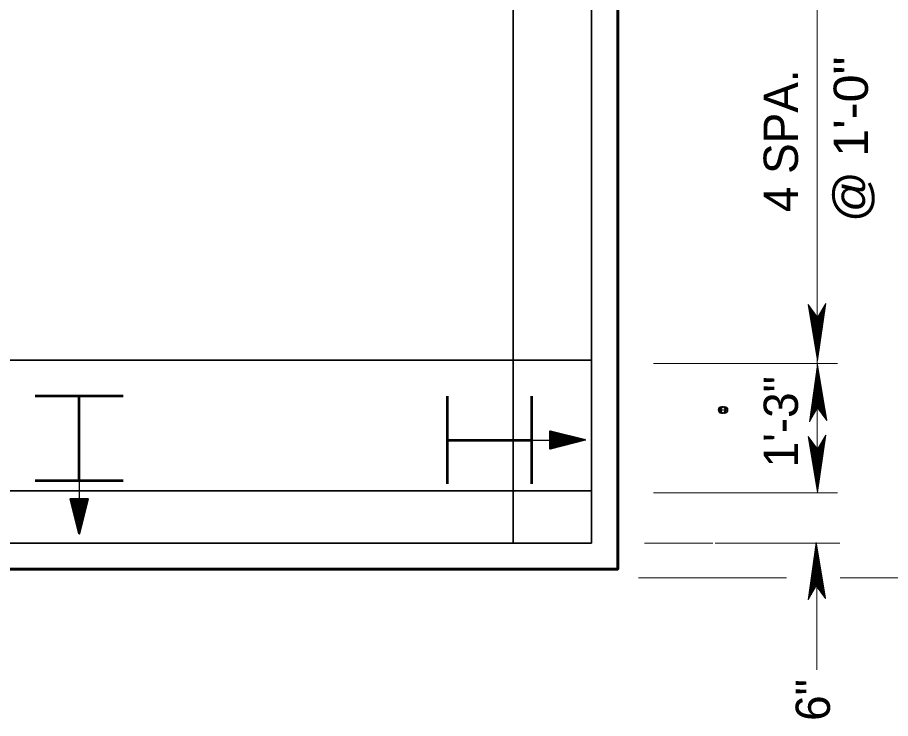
# Model space of a CAD drawing. Extents: x 144 to 252, y 360 to 425.
# Drawn here: x 174.56 to 182.91, y 391.03 to 397.74 of the extents above; entities that cross this region are included whole.
import ezdxf
from ezdxf.enums import TextEntityAlignment as Align

# ---------------------------------------------------------------- set-up
doc = ezdxf.new("R2010")
doc.units = 0
doc.header["$LTSCALE"] = 0.13
doc.header["$PDMODE"] = 32
doc.header["$PDSIZE"] = 0.065
for name, color, linetype, lineweight in [('1', 7, 'Continuous', 40), ('10', 7, 'Continuous', 35), ('16', 7, 'Continuous', 13), ('3', 7, 'Continuous', 13), ('9', 7, 'Continuous', 25)]:
    doc.layers.add(name, color=color, linetype=linetype, lineweight=lineweight)

msp = doc.modelspace()

# ---------------------------------------------------------------- linework, layer by layer
at = {"layer": '1', "lineweight": 35}
for p, q in [((179.2978, 397.8819), (179.2978, 392.7095)), ((179.2978, 395.4595), (179.2978, 395.8819)), ((180.0478, 395.4595), (180.0478, 392.7095)), ((168.4074, 394.4595), (180.0478, 394.4595)), ((168.4074, 393.2095), (180.0478, 393.2095)), ((168.3901, 392.7095), (180.0478, 392.7095))]:
    msp.add_line(p, q, dxfattribs=at)
at = {"layer": '1', "lineweight": 13}
for p, q in [((182.2047, 397.8819), (182.2047, 393.2256)), ((182.2047, 395.4595), (182.2047, 395.8819)), ((182.3986, 394.4261), (180.6381, 394.4261)), ((181.7029, 393.1902), (180.6381, 393.1902)), ((182.3986, 393.1902), (181.4498, 393.1902)), ((181.2062, 392.7091), (180.5544, 392.7091)), ((182.4215, 392.7091), (181.2307, 392.7091)), ((182.2047, 392.6491), (182.2047, 392.3438)), ((182.2006, 392.5937), (182.2006, 391.4952)), ((181.9128, 392.3779), (180.4962, 392.3779)), ((184.4158, 392.3779), (182.4244, 392.3779))]:
    msp.add_line(p, q, dxfattribs=at)
at = {"layer": '1', "lineweight": 60}
for p, q in [((180.2978, 395.8819), (180.2978, 395.4595)), ((180.2978, 392.4595), (180.2978, 395.8819)), ((180.2978, 393.9828), (180.2978, 392.4595)), ((180.2978, 392.4595), (156.2978, 392.4595)), ((156.2978, 392.4595), (180.2978, 392.4595))]:
    msp.add_line(p, q, dxfattribs=at)
at = {"layer": '1', "lineweight": 53}
for p, q in [((174.7277, 394.1175), (175.5673, 394.1175)), ((175.1474, 393.3092), (175.1474, 394.1175)), ((178.6658, 394.1148), (178.6658, 393.2752)), ((179.4742, 394.1148), (179.4742, 393.2752)), ((178.6658, 393.695), (179.4742, 393.695)), ((174.7276, 393.3092), (175.5672, 393.3092))]:
    msp.add_line(p, q, dxfattribs=at)
at = {"layer": '1', "lineweight": 25}
for p, q in [((179.4742, 393.695), (179.9742, 393.695)), ((175.1474, 393.3092), (175.1474, 392.8092))]:
    msp.add_line(p, q, dxfattribs=at)
at = {"layer": '1', "lineweight": 35}
msp.add_lwpolyline([(180.0478, 395.4595), (180.0478, 397.8819), (180.0478, 400.2095)], dxfattribs=at)
at = {"layer": '1', "lineweight": 60}
msp.add_lwpolyline([(156.2978, 392.4595), (180.2978, 392.4595), (180.2978, 397.8819)], dxfattribs=at)
at = {"layer": '10'}
for p, q in [((179.652, 393.7432), (179.8246, 393.7359)), ((179.8359, 393.7103), (179.652, 393.718)), ((179.8358, 393.704), (179.652, 393.7117)), ((179.652, 393.7054), (179.8357, 393.6977)), ((179.8355, 393.6915), (179.652, 393.6992)), ((179.652, 393.6954), (179.9872, 393.6954)), ((175.1439, 392.9478), (175.1516, 393.1313)), ((175.1478, 393.1313), (175.1478, 392.7961)), ((175.1578, 393.1313), (175.1502, 392.9477)), ((175.1564, 392.9475), (175.1642, 393.1313)), ((175.1627, 392.9474), (175.1704, 393.1313)), ((175.1956, 393.1313), (175.1883, 392.9588))]:
    msp.add_line(p, q, dxfattribs=at)
for points in [[(179.652, 393.6119), (179.652, 393.7788), (179.9872, 393.6955)], [(179.652, 393.6119), (179.9872, 393.6955), (179.652, 393.6119)], [(175.0643, 393.1313), (175.2312, 393.1313), (175.1479, 392.7961)], [(175.0643, 393.1313), (175.1479, 392.7961), (175.0643, 393.1313)]]:
    msp.add_lwpolyline(points, dxfattribs=at)
for points in [[(179.9872, 393.6955), (179.652, 393.6119), (179.652, 393.7788), (179.652, 393.6119)], [(175.1479, 392.7961), (175.0643, 393.1313), (175.2312, 393.1313), (175.0643, 393.1313)]]:
    msp.add_lwpolyline(points, close=True, dxfattribs=at)
at = {"layer": '3'}
for p, q in [((182.2086, 394.4528), (182.1193, 394.9905)), ((182.1193, 394.9905), (182.2084, 394.868)), ((182.2079, 394.4672), (182.1217, 394.9872)), ((182.2079, 394.4781), (182.124, 394.984)), ((182.2079, 394.4925), (182.1272, 394.9797)), ((182.2079, 394.5052), (182.1298, 394.976)), ((182.2828, 394.9956), (182.2079, 394.4672)), ((182.2808, 394.9921), (182.2079, 394.4781)), ((182.2782, 394.9875), (182.2079, 394.4925)), ((182.2757, 394.9834), (182.2079, 394.5052)), ((182.2757, 394.9834), (182.2079, 394.5052)), ((182.2736, 394.9797), (182.2079, 394.5166)), ((182.2084, 394.868), (182.2863, 395.0016)), ((182.2863, 395.0016), (182.2086, 394.4528)), ((182.2079, 394.5166), (182.1322, 394.9727)), ((182.2079, 394.531), (182.1354, 394.9684)), ((182.2079, 394.5437), (182.1382, 394.9647)), ((182.2079, 394.5575), (182.1411, 394.9606)), ((182.2079, 394.5713), (182.1441, 394.9565)), ((182.2079, 394.5846), (182.1469, 394.9526)), ((182.2079, 394.5985), (182.1499, 394.9485)), ((182.2079, 394.6111), (182.1526, 394.9447)), ((182.2079, 394.6225), (182.1551, 394.9413)), ((182.2079, 394.6382), (182.1584, 394.9367)), ((182.2079, 394.652), (182.1614, 394.9327)), ((182.2074, 394.67), (182.1645, 394.9284)), ((182.2074, 394.6839), (182.1675, 394.9242)), ((182.2074, 394.6971), (182.1703, 394.9204)), ((182.2079, 394.7062), (182.1731, 394.9167)), ((182.2079, 394.7182), (182.1757, 394.9131)), ((182.2079, 394.732), (182.1787, 394.909)), ((182.2079, 394.7477), (182.1819, 394.9043)), ((182.2079, 394.7602), (182.1847, 394.9007)), ((182.2079, 394.7735), (182.1875, 394.8967)), ((182.2079, 394.7855), (182.1902, 394.8932)), ((182.2441, 394.9292), (182.2074, 394.67)), ((182.2415, 394.9247), (182.2074, 394.6839)), ((182.239, 394.9205), (182.2074, 394.6971)), ((182.2709, 394.9752), (182.2079, 394.531)), ((182.2685, 394.9711), (182.2079, 394.5437)), ((182.266, 394.9667), (182.2079, 394.5575)), ((182.2634, 394.9622), (182.2079, 394.5713)), ((182.2609, 394.958), (182.2079, 394.5846)), ((182.2583, 394.9535), (182.2079, 394.5985)), ((182.256, 394.9495), (182.2079, 394.6111)), ((182.2537, 394.9457), (182.2079, 394.6225)), ((182.2509, 394.9407), (182.2079, 394.6382)), ((182.2482, 394.9363), (182.2079, 394.652)), ((182.2382, 394.919), (182.2079, 394.7062)), ((182.2359, 394.9151), (182.2079, 394.7182)), ((182.2332, 394.9107), (182.2079, 394.732)), ((182.2304, 394.9057), (182.2079, 394.7477)), ((182.228, 394.9016), (182.2079, 394.7602)), ((182.2255, 394.8973), (182.2079, 394.7735)), ((182.2233, 394.8935), (182.2079, 394.7855)), ((182.246, 394.9323), (182.209, 394.6716)), ((182.2079, 394.8), (182.1932, 394.8889)), ((182.2079, 394.8138), (182.1962, 394.8847)), ((182.2079, 394.8265), (182.1989, 394.8811)), ((182.2079, 394.8397), (182.2018, 394.8772)), ((182.2079, 394.8512), (182.2042, 394.8737)), ((182.2079, 394.8613), (182.2064, 394.8707)), ((182.2206, 394.8888), (182.2079, 394.8)), ((182.218, 394.8844), (182.2079, 394.8138)), ((182.2157, 394.8803), (182.2079, 394.8265)), ((182.211, 394.8724), (182.2079, 394.8512)), ((182.2086, 394.8682), (182.2086, 394.4528)), ((182.2126, 394.8751), (182.209, 394.85)), ((182.1308, 393.87), (182.2086, 394.4187)), ((182.1343, 393.876), (182.2092, 394.4043)), ((182.1363, 393.8795), (182.2092, 394.3935)), ((182.2086, 394.4187), (182.2978, 393.8811)), ((182.2086, 394.0033), (182.2086, 394.4187)), ((182.2092, 394.4043), (182.2955, 393.8843)), ((182.2092, 394.3935), (182.2932, 393.8876)), ((182.139, 393.8841), (182.2092, 394.3791)), ((182.1414, 393.8882), (182.2092, 394.3663)), ((182.1414, 393.8882), (182.2092, 394.3663)), ((182.1436, 393.8918), (182.2092, 394.355)), ((182.1462, 393.8964), (182.2092, 394.3406)), ((182.1487, 393.9005), (182.2092, 394.3278)), ((182.1512, 393.9049), (182.2092, 394.3141)), ((182.2092, 394.3791), (182.29, 393.8918)), ((182.2092, 394.3663), (182.2873, 393.8956)), ((182.2092, 394.355), (182.2849, 393.8989)), ((182.2092, 394.3406), (182.2817, 393.9032)), ((182.2092, 394.3278), (182.279, 393.9069)), ((182.2092, 394.3141), (182.2761, 393.911)), ((182.1538, 393.9093), (182.2092, 394.3003)), ((182.1562, 393.9136), (182.2092, 394.287)), ((182.1589, 393.9181), (182.2092, 394.2731)), ((182.1612, 393.9221), (182.2092, 394.2605)), ((182.1634, 393.9258), (182.2092, 394.2491)), ((182.1662, 393.9308), (182.2092, 394.2334)), ((182.2092, 394.3003), (182.2731, 393.9151)), ((182.2092, 394.287), (182.2703, 393.919)), ((182.2092, 394.2731), (182.2672, 393.9231)), ((182.2092, 394.2605), (182.2646, 393.9268)), ((182.2092, 394.2491), (182.2621, 393.9303)), ((182.2092, 394.2334), (182.2587, 393.9348)), ((182.1689, 393.9352), (182.2092, 394.2196)), ((182.1712, 393.9392), (182.2082, 394.2)), ((182.1731, 393.9424), (182.2097, 394.2016)), ((182.1757, 393.9468), (182.2097, 394.1877)), ((182.1782, 393.9511), (182.2097, 394.1745)), ((182.179, 393.9526), (182.2092, 394.1654)), ((182.1813, 393.9565), (182.2092, 394.1534)), ((182.2092, 394.2196), (182.2558, 393.9389)), ((182.2092, 394.1654), (182.2441, 393.9549)), ((182.2092, 394.1534), (182.2415, 393.9585)), ((182.2097, 394.2016), (182.2527, 393.9432)), ((182.2097, 394.1877), (182.2497, 393.9473)), ((182.2097, 394.1745), (182.2468, 393.9512)), ((182.1839, 393.9609), (182.2092, 394.1396)), ((182.1867, 393.9659), (182.2092, 394.1239)), ((182.1892, 393.97), (182.2092, 394.1113)), ((182.1917, 393.9742), (182.2092, 394.0981)), ((182.1939, 393.9781), (182.2092, 394.0861)), ((182.1966, 393.9828), (182.2092, 394.0716)), ((182.1992, 393.9872), (182.2092, 394.0577)), ((182.2092, 394.1396), (182.2385, 393.9626)), ((182.2092, 394.1239), (182.2353, 393.9672)), ((182.2092, 394.1113), (182.2325, 393.9709)), ((182.2092, 394.0981), (182.2297, 393.9748)), ((182.2092, 394.0861), (182.227, 393.9784)), ((182.2092, 394.0716), (182.224, 393.9827)), ((182.2092, 394.0577), (182.221, 393.9868)), ((182.2087, 394.0036), (182.1308, 393.87)), ((182.2015, 393.9912), (182.2092, 394.0451)), ((182.2046, 393.9965), (182.2082, 394.0216)), ((182.2062, 393.9992), (182.2092, 394.0204)), ((182.2978, 393.8811), (182.2087, 394.0036)), ((182.2092, 394.0451), (182.2182, 393.9905)), ((182.2092, 394.0318), (182.2154, 393.9944)), ((182.2092, 394.0204), (182.213, 393.9978)), ((182.2092, 394.0102), (182.2107, 394.0008)), ((182.2086, 393.1918), (182.1193, 393.7295)), ((182.1193, 393.7295), (182.2084, 393.607)), ((182.2079, 393.2063), (182.1217, 393.7262)), ((182.2828, 393.7346), (182.2079, 393.2063)), ((182.2808, 393.7311), (182.2079, 393.2171)), ((182.2782, 393.7265), (182.2079, 393.2315)), ((182.2084, 393.607), (182.2863, 393.7406)), ((182.2863, 393.7406), (182.2086, 393.1918)), ((182.2079, 393.2171), (182.124, 393.723)), ((182.2079, 393.2315), (182.1272, 393.7188)), ((182.2079, 393.2442), (182.1298, 393.715)), ((182.2079, 393.2556), (182.1322, 393.7117)), ((182.2079, 393.27), (182.1354, 393.7074)), ((182.2079, 393.2827), (182.1382, 393.7037)), ((182.2079, 393.2965), (182.1411, 393.6996)), ((182.2079, 393.3103), (182.1441, 393.6955)), ((182.2079, 393.3236), (182.1469, 393.6916)), ((182.2079, 393.3375), (182.1499, 393.6875)), ((182.2079, 393.3501), (182.1526, 393.6837)), ((182.2079, 393.3615), (182.1551, 393.6803)), ((182.2079, 393.3772), (182.1584, 393.6757)), ((182.2079, 393.391), (182.1614, 393.6717)), ((182.2074, 393.409), (182.1645, 393.6674)), ((182.2074, 393.4229), (182.1675, 393.6633)), ((182.2074, 393.4361), (182.1703, 393.6594)), ((182.2079, 393.4452), (182.1731, 393.6557)), ((182.2079, 393.4572), (182.1757, 393.6521)), ((182.2079, 393.471), (182.1787, 393.648)), ((182.2079, 393.4867), (182.1819, 393.6433)), ((182.2441, 393.6682), (182.2074, 393.409)), ((182.2415, 393.6637), (182.2074, 393.4229)), ((182.239, 393.6595), (182.2074, 393.4361)), ((182.2757, 393.7224), (182.2079, 393.2442)), ((182.2757, 393.7224), (182.2079, 393.2442)), ((182.2736, 393.7188), (182.2079, 393.2556)), ((182.2709, 393.7142), (182.2079, 393.27)), ((182.2685, 393.7101), (182.2079, 393.2827)), ((182.266, 393.7057), (182.2079, 393.2965)), ((182.2634, 393.7012), (182.2079, 393.3103)), ((182.2609, 393.697), (182.2079, 393.3236)), ((182.2583, 393.6925), (182.2079, 393.3375)), ((182.256, 393.6885), (182.2079, 393.3501)), ((182.2537, 393.6848), (182.2079, 393.3615)), ((182.2509, 393.6798), (182.2079, 393.3772)), ((182.2482, 393.6753), (182.2079, 393.391)), ((182.2382, 393.658), (182.2079, 393.4452)), ((182.2359, 393.6541), (182.2079, 393.4572)), ((182.2332, 393.6497), (182.2079, 393.471)), ((182.2304, 393.6447), (182.2079, 393.4867)), ((182.228, 393.6406), (182.2079, 393.4992)), ((182.246, 393.6713), (182.209, 393.4106)), ((182.2079, 393.4992), (182.1847, 393.6397)), ((182.2079, 393.5125), (182.1875, 393.6357)), ((182.2079, 393.5245), (182.1902, 393.6322)), ((182.2079, 393.539), (182.1932, 393.6279)), ((182.2079, 393.5528), (182.1962, 393.6237)), ((182.2079, 393.5655), (182.1989, 393.6201)), ((182.2079, 393.5788), (182.2018, 393.6162)), ((182.2079, 393.5902), (182.2042, 393.6128)), ((182.2079, 393.6003), (182.2064, 393.6097)), ((182.2255, 393.6363), (182.2079, 393.5125)), ((182.2233, 393.6325), (182.2079, 393.5245)), ((182.2206, 393.6278), (182.2079, 393.539)), ((182.218, 393.6234), (182.2079, 393.5528)), ((182.2157, 393.6193), (182.2079, 393.5655)), ((182.211, 393.6114), (182.2079, 393.5902)), ((182.2086, 393.6072), (182.2086, 393.1918)), ((182.2126, 393.6141), (182.209, 393.589)), ((182.1186, 392.1662), (182.1963, 392.7149)), ((182.1221, 392.1722), (182.197, 392.7005)), ((182.1241, 392.1757), (182.197, 392.6897)), ((182.1267, 392.1803), (182.197, 392.6753)), ((182.1292, 392.1843), (182.197, 392.6625)), ((182.1292, 392.1843), (182.197, 392.6625)), ((182.1313, 392.188), (182.197, 392.6512)), ((182.1963, 392.7149), (182.2856, 392.1773)), ((182.1963, 392.2995), (182.1963, 392.7149)), ((182.197, 392.7005), (182.2832, 392.1805)), ((182.197, 392.6897), (182.2809, 392.1837)), ((182.197, 392.6753), (182.2777, 392.188)), ((182.197, 392.6625), (182.2751, 392.1918)), ((182.197, 392.6512), (182.2727, 392.1951)), ((182.134, 392.1926), (182.197, 392.6368)), ((182.1364, 392.1967), (182.197, 392.624)), ((182.1389, 392.2011), (182.197, 392.6103)), ((182.1415, 392.2055), (182.197, 392.5964)), ((182.144, 392.2097), (182.197, 392.5832)), ((182.1467, 392.2142), (182.197, 392.5693)), ((182.1489, 392.2183), (182.197, 392.5567)), ((182.197, 392.6368), (182.2695, 392.1993)), ((182.197, 392.624), (182.2668, 392.2031)), ((182.197, 392.6103), (182.2638, 392.2072)), ((182.197, 392.5964), (182.2608, 392.2113)), ((182.197, 392.5832), (182.258, 392.2152)), ((182.197, 392.5693), (182.255, 392.2192)), ((182.197, 392.5567), (182.2523, 392.223)), ((182.1512, 392.222), (182.197, 392.5453)), ((182.154, 392.227), (182.197, 392.5296)), ((182.1567, 392.2314), (182.197, 392.5157)), ((182.1589, 392.2354), (182.1959, 392.4962)), ((182.1608, 392.2386), (182.1975, 392.4977)), ((182.1634, 392.243), (182.1975, 392.4838)), ((182.197, 392.5453), (182.2498, 392.2264)), ((182.197, 392.5296), (182.2465, 392.231)), ((182.197, 392.5157), (182.2435, 392.2351)), ((182.1975, 392.4977), (182.2404, 392.2393)), ((182.1975, 392.4838), (182.2374, 392.2435)), ((182.1659, 392.2473), (182.1975, 392.4707)), ((182.1668, 392.2487), (182.197, 392.4616)), ((182.169, 392.2527), (182.197, 392.4496)), ((182.1717, 392.2571), (182.197, 392.4357)), ((182.1745, 392.2621), (182.197, 392.4201)), ((182.1769, 392.2662), (182.197, 392.4075)), ((182.1794, 392.2704), (182.197, 392.3942)), ((182.197, 392.4616), (182.2318, 392.2511)), ((182.197, 392.4496), (182.2293, 392.2547)), ((182.197, 392.4357), (182.2262, 392.2587)), ((182.197, 392.4201), (182.223, 392.2634)), ((182.197, 392.4075), (182.2202, 392.2671)), ((182.197, 392.3942), (182.2174, 392.271)), ((182.1975, 392.4707), (182.2346, 392.2473)), ((182.1817, 392.2742), (182.197, 392.3822)), ((182.1843, 392.2789), (182.197, 392.3678)), ((182.1869, 392.2833), (182.197, 392.3539)), ((182.1892, 392.2874), (182.197, 392.3413)), ((182.1923, 392.2927), (182.1959, 392.3177)), ((182.1939, 392.2953), (182.197, 392.3166)), ((182.197, 392.3822), (182.2147, 392.2746)), ((182.197, 392.3678), (182.2117, 392.2788)), ((182.197, 392.3539), (182.2087, 392.283)), ((182.197, 392.3413), (182.206, 392.2867)), ((182.197, 392.328), (182.2032, 392.2906)), ((182.197, 392.3166), (182.2007, 392.294)), ((182.197, 392.3064), (182.1985, 392.297)), ((182.1965, 392.2997), (182.1186, 392.1662)), ((182.2856, 392.1773), (182.1965, 392.2997))]:
    msp.add_line(p, q, dxfattribs=at)
for p in [(181.2904, 393.9828), (181.2928, 393.9828), (181.2952, 393.9828), (181.2978, 393.9828), (181.2997, 393.9828), (181.3017, 393.9828), (181.3108, 393.9828), (181.3153, 393.9828), (181.3193, 393.9828)]:
    msp.add_point(p, dxfattribs=at)
at = {"layer": '9'}
for p, q in [((179.6727, 393.7738), (179.652, 393.7746)), ((179.703, 393.7662), (179.652, 393.7683)), ((179.7334, 393.7586), (179.652, 393.762)), ((179.7638, 393.7511), (179.652, 393.7557)), ((179.7943, 393.7435), (179.652, 393.7495)), ((179.8364, 393.7292), (179.652, 393.7369)), ((179.8363, 393.7228), (179.652, 393.7306)), ((179.8361, 393.7166), (179.652, 393.7242)), ((179.855, 393.7284), (179.8364, 393.7292)), ((179.8353, 393.6852), (179.652, 393.6928)), ((179.8352, 393.6789), (179.652, 393.6866)), ((179.835, 393.6726), (179.652, 393.6803)), ((179.8348, 393.6663), (179.652, 393.674)), ((179.8347, 393.6601), (179.652, 393.6677)), ((179.822, 393.6543), (179.652, 393.6614)), ((179.8004, 393.6489), (179.652, 393.6552)), ((179.7788, 393.6436), (179.652, 393.6488)), ((179.7572, 393.6382), (179.652, 393.6425)), ((179.8436, 393.6597), (179.8347, 393.6601)), ((179.8653, 393.6651), (179.8348, 393.6663)), ((179.8868, 393.6705), (179.835, 393.6726)), ((179.9084, 393.6758), (179.8352, 393.6789)), ((179.93, 393.6812), (179.8353, 393.6852)), ((179.9516, 393.6866), (179.8355, 393.6915)), ((179.9733, 393.692), (179.8357, 393.6977)), ((179.9766, 393.6982), (179.8358, 393.704)), ((179.9462, 393.7057), (179.8359, 393.7103)), ((179.9158, 393.7132), (179.8361, 393.7166)), ((179.8854, 393.7208), (179.8363, 393.7228)), ((179.7357, 393.6327), (179.652, 393.6362)), ((179.7141, 393.6274), (179.652, 393.63)), ((179.6924, 393.622), (179.652, 393.6237)), ((179.6708, 393.6166), (179.652, 393.6174)), ((175.069, 393.1125), (175.0698, 393.1313)), ((175.0744, 393.0909), (175.0761, 393.1313)), ((175.0798, 393.0693), (175.0824, 393.1313)), ((175.0852, 393.0477), (175.0887, 393.1313)), ((175.0906, 393.0261), (175.0949, 393.1313)), ((175.096, 393.0045), (175.1012, 393.1313)), ((175.1013, 392.9829), (175.1076, 393.1313)), ((175.1068, 392.9613), (175.1138, 393.1313)), ((175.1125, 392.9487), (175.1201, 393.1313)), ((175.1188, 392.9485), (175.1264, 393.1313)), ((175.125, 392.9483), (175.1327, 393.1313)), ((175.1313, 392.9482), (175.139, 393.1313)), ((175.1376, 392.948), (175.1453, 393.1313)), ((175.169, 392.9472), (175.1767, 393.1313)), ((175.1753, 392.9471), (175.183, 393.1313)), ((175.1816, 392.9469), (175.1893, 393.1313)), ((175.1959, 392.9891), (175.2019, 393.1313)), ((175.2035, 393.0195), (175.2082, 393.1313)), ((175.211, 393.0499), (175.2144, 393.1313)), ((175.2186, 393.0803), (175.2207, 393.1313)), ((175.2262, 393.1107), (175.227, 393.1313)), ((175.1122, 392.9398), (175.1125, 392.9487)), ((175.1175, 392.9181), (175.1188, 392.9485)), ((175.1229, 392.8965), (175.125, 392.9483)), ((175.1282, 392.8749), (175.1313, 392.9482)), ((175.1337, 392.8533), (175.1376, 392.948)), ((175.139, 392.8317), (175.1439, 392.9478)), ((175.1444, 392.8101), (175.1502, 392.9477)), ((175.1506, 392.8067), (175.1564, 392.9475)), ((175.1581, 392.8372), (175.1627, 392.9474)), ((175.1657, 392.8676), (175.169, 392.9472)), ((175.1732, 392.8979), (175.1753, 392.9471)), ((175.1808, 392.9283), (175.1816, 392.9469))]:
    msp.add_line(p, q, dxfattribs=at)
at = {"layer": '9', "lineweight": 40}
for points in [[(179.9872, 393.6955), (179.652, 393.6119), (179.652, 393.7788)], [(175.1479, 392.7961), (175.0643, 393.1313), (175.2312, 393.1313)]]:
    msp.add_lwpolyline(points, close=True, dxfattribs=at)

# ---------------------------------------------------------------- texts
at = {"layer": '16', "width": 1.1}
msp.add_text('@ 1\'-0"', height=0.3281, rotation=90, dxfattribs=at).set_placement((182.6902, 396.5721), align=Align.CENTER)
at = {"layer": '16'}
for s, p in [('4 SPA.', (182.0209, 396.5584)), ('1\'-3"', (182.0209, 393.8699))]:
    msp.add_text(s, height=0.3281, rotation=90, dxfattribs=at).set_placement(p, align=Align.CENTER)
msp.add_text('6"', height=0.3281, rotation=90, dxfattribs=at).set_placement((182.3268, 391.4076), align=Align.RIGHT)

doc.saveas('drawing.dxf')
